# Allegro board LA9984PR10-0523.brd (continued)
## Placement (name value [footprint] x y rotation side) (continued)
PC803  -  [C_0603]  207.1 63.74 90 bottom
PC804  -  [C_0805]  212.73 73.84 0 top
PC805  -  [C_0805]  212.73 71.87 0 top
PC806  -  [C_0402]  204.23 53.96 0 bottom
PC807  -  [C_0603]  202.47 63.68 0 bottom
PC808  -  [C_0805]  212.73 69.92 0 top
PC809  -  [C_0402]  201.51 56.64 270 bottom
PC810  -  [C_0603]  201.51 59.49 180 top
PC811  -  [C_0603]  203.42 59.5 270 top
PC813  -  [C_0402]  205.32 57.28 270 top
PC814  -  [C_0402]  204.23 53.07 0 bottom
PC815  -  [C_0603]  211.61 64.24 0 bottom
PC816  -  [C_0402]  201.58 57.51 90 top
PC817  -  [C_0402]  201.58 53.06 90 bottom
PC818  -  [C_0402]  206.04 55.74 180 bottom
PC819  -  [C_0402]  199.11 61.27 180 bottom
PC820  -  [C_0402]  199.11 60.38 180 bottom
PC821  -  [C_0402]  201.59 56.63 180 top
PC831  -  [C_0402]  213.38 76.06 0 top
PC832  -  [C_0402]  213.38 75.17 0 top
PC835  -  [C_0603]  194.53 91.17 90 top
PC836  -  [C_D1]  204.31 87.44 270 top
PC837  -  [C_D1]  209.07 87.44 270 top
PC838  -  [C_D1]  198.15 86.61 270 bottom
PC839  -  [C_D1]  193.39 86.61 270 bottom
PC840  -  [C_0402]  181.44 124.21 0 top
PC841  -  [C_0402]  181.5 119.7 0 top
PC842  -  [C_0402]  182.08 120.94 90 top
PC843  -  [C_0402]  179.54 119.7 0 top
PC844  -  [C_0402]  177.34 119.25 180 top
PC845  -  [C_0402]  177.34 120.71 180 top
PC846  -  [C_0402]  176.49 122.68 0 top
PC847  -  [C_0402]  179.59 117.97 0 top
PC848  -  [C_0402]  181.37 117.97 0 top
PC849  -  [C_0402]  173.88 104.21 270 bottom
PC850  -  [C_0402]  178.21 121.86 270 top
PC851  -  [C_0402]  179.09 121.46 0 top
PC852  -  [C_0402]  178.73 117.72 180 top
PC853  -  [C_0402]  175.43 122.68 180 top
PC854  -  [C_0402]  174.46 119.25 0 top
PC855  -  [C_0402]  175.43 124.14 180 top
PC856  -  [C_0402]  179.28 124.21 0 top
PC857  -  [C_0402]  179.34 125.67 0 top
PC858  -  [C_0402]  181.44 125.67 0 top
PC859  -  [C_0402]  179.28 122.75 0 top
PC860  -  [C_0402]  181.44 122.75 0 top
PC861  -  [C_0402]  176.95 117.72 180 top
PC862  -  [C_0402]  178.2 114.48 0 top
PC863  -  [C_0402]  175.17 117.72 180 top
PC864  -  [C_0402]  176.36 124.14 0 top
PC865  -  [C_0402]  176.49 125.64 0 top
PC866  -  [C_0402]  174.46 120.71 0 top
PC867  -  [C_0603]  192.81 91.17 90 top
PC868  -  [C_0603]  196.31 91.17 90 top
PC869  -  [C_0402]  207.62 58.22 180 top
PC870  -  [C_0603]  198.02 91.17 90 top
PC871  -  [C_0402]  173.58 119.56 90 top
PC872  -  [C_0402]  172.18 119.03 90 top
PC873  -  [C_0402]  172.18 121.74 270 top
PC901  -  [C_0805]  97.44 124.74 90 top
PC902  -  [C_0805]  100.3 124.68 90 top
PC903  -  [C_0805]  102.77 124.68 90 top
PC904  -  [C_0805]  105.31 124.68 90 top
PC905  -  [C_0805]  107.79 124.68 90 top
PC906  -  [C_0805]  110.33 124.68 90 top
PC907  -  [C_0805]  112.8 124.68 90 top
PC908  -  [C_0805]  96.93 119.91 90 top
PC909  -  [C_0805]  100.65 139.56 0 top
PC910  -  [C_0805]  96.87 116.8 90 top
PC911  -  [C_0805]  97.35 137.34 0 top
PC912  -  [C_0805]  110.81 137.34 0 top
PC913  -  [C_0805]  110.75 139.5 0 top
PC914  -  [C_0805]  107.45 137.34 0 top
PC915  -  [C_0805]  107.38 139.5 0 top
PC916  -  [C_0805]  104.08 137.34 0 top
PC917  -  [C_0805]  100.71 137.34 0 top
PC918  -  [C_0805]  110.81 135.94 0 bottom
PC919  -  [C_0805]  107.45 135.94 0 bottom
PC920  -  [C_0805]  104.08 135.94 0 bottom
PC921  -  [C_0805]  100.71 135.94 0 bottom
PC922  -  [C_0805]  103.95 139.56 0 top
PC923  -  [C_0805]  97.35 135.94 0 bottom
PC1100  -  [C_0402]  178.64 175.38 0 top
PC1101  -  [C_0402]  178.64 176.26 0 top
PC1102  -  [C_0805]  178.82 177.6 0 top
PC1103  -  [C_0603]  183.16 172.26 90 top
PC1104  -  [C_0402]  188.19 174.04 180 bottom
PC1105  -  [C_0603]  183.67 175.06 90 top
PC1106  -  [C_0402]  181.45 172.12 90 top
PC1108  -  [C_MP6VU330MC6]  182.65 169.15 0 bottom
PC1200  -  [C_0402]  185.08 180.34 180 top
PC1201  -  [C_0805]  194.81 188.92 180 top
PC1202  -  [C_0805]  188.71 178.12 180 bottom
PC1203  -  [C_0402]  192.43 181.09 90 bottom
PC1204  -  [C_0805]  191.1 181.27 90 bottom
PC1205  -  [C_0603]  185.83 178.56 270 bottom
PC1206  -  [C_0805]  194.81 187.2 180 top
PC1207  -  [C_0805]  196.24 188.38 90 top
PC1209  -  [C_0402]  189.77 177.82 270 bottom
PC1210  -  [C_0603]  188.56 181.36 90 top
PC1211  -  [C_0805]  194.81 185.49 180 top
PC1212  -  [C_0603]  188.62 189.93 0 top
PC1213  -  [C_0603]  184.62 178.56 270 bottom
PC1214  -  [C_0402]  174.27 180.77 90 bottom
PC1300  -  [C_0805]  199.1 75.39 270 top
PC1301  -  [C_0805]  195 62.73 180 bottom
PC1302  -  [C_0402]  194.67 64.63 180 top
PC1303  -  [C_0805]  193.64 75.39 270 top
PC1304  -  [C_0402]  197.15 67.04 180 top
PC1305  -  [C_0805]  197.32 75.39 270 top
PC1306  -  [C_0402]  197.77 65.53 270 top
PC1307  -  [C_0402]  196.94 67.12 270 bottom
PC1308  -  [C_0805]  195.55 75.39 270 top
PD1  -  [IP4223CZ6_SO6]  142.24 187.06 270 bottom
PD2  -  [TVNST52302AB0_SOT523-3]  141.57 190.12 180 bottom
PD3  -  [TVNST52302AB0_SOT523-3]  144.87 187.45 270 bottom
PD101  -  [L03ESDL5V0CG3-2_SOT-523-3]  204.75 25.84 0 top
PD701  -  [RB751V-40_SOD323-2]  162.53 173.03 0 top
PH1  -  [R_0402]  106.19 115.75 0 top
PH501  -  [R_0402]  95.58 145.47 0 bottom
PH502  -  [R_0402]  111.93 146.17 180 bottom
PH800  -  [R_0402]  203.42 81.1 270 bottom
PJP100  -  [JUMP_43X118]  201.22 13.46 180 bottom
PJP101  -  [JUMP_43X118]  201.1 25.59 180 bottom
PJP102  -  [JUMP_43X118]  201.22 8.19 180 bottom
PJP103  -  [JUMP_43X118]  201.1 30.86 180 bottom
PJP200  -  [JUMP_43X118]  149.32 29.86 90 top
PJP201  -  [JUMP_43X118]  144.81 29.62 90 bottom
PJP203  -  [JUMP_43X39]  155.03 31.37 270 bottom
PJP300  -  [JUMP_43X118]  143.67 142.46 270 top
PJP400  -  [JUMP_43X79]  107.97 13.18 90 bottom
PJP401  -  [JUMP_43X79]  107.64 28.51 90 bottom
PJP600  -  [JUMP_43X79]  213.22 93.6 0 bottom
PJP601  -  [JUMP_43X79]  215.29 98.77 270 top
PJP1100  -  [JUMP_43X118]  182.78 164.33 270 bottom
PJP1101  -  [JUMP_43X118]  188.12 164.33 270 bottom
PJP1200  -  [JUMP_43X118]  194.47 183.31 270 top
PJP1300  -  [JUMP_43X79]  195.74 78.2 270 top
PJP1301  -  [JUMP_43X79]  194.66 60.77 270 bottom
PJPDC  -  [ACES_50299-00501-003_5P]  136.9 180.4 270 bottom
PL1  -  [CHT_C8BBPH853025_2P]  140.43 176.01 270 bottom
PL2  -  [CHT_C8BBPH853025_2P]  132.93 184.52 180 bottom
PL3  -  [CHENG_SMB3025500YA_2P]  155.86 182.27 90 bottom
PL4  -  [CHT_C8BBPH853025_2P]  132.87 168.14 180 bottom
PL100  -  [VISHAY_IHLP-2525CZ-01_2P]  214.79 10.16 180 bottom
PL101  -  [VISHAY_IHLP-2525CZ-01_2P]  215.93 31.63 180 bottom
PL102  -  [CYNTE_PCMB053T-1R0MS_2P]  222.5 20.64 180 bottom
PL200  -  [TAI-T_VMPI0703AR-1R0M-Z01_2P]  145.4 17.13 0 bottom
PL201  -  [L_1812-1806]  165.32 22.7 270 bottom
PL301  -  [CYNTE_PCMB063T-1R0MS_2P]  144.08 152.6 270 bottom
PL302  -  [L_1812-1806]  134.42 160.33 0 bottom
PL400  -  [TAIYO_NRS4018T1R0NDGJ_2P]  106.94 22.79 90 bottom
PL501  -  [L_1812-1806]  135.09 148.54 90 bottom
PL502  -  [TOKO_FDUE1040J-H-R36M-P3_4P]  109.67 142.17 180 bottom
PL600  -  [TAIYO_NRS4018T1R0NDGJ_2P]  219.55 96.84 90 bottom
PL701  -  [TOKO_FDVE1040-H-2R2M-P3_2P]  155.38 174.61 180 bottom
PL702  -  [CYNTE_PCMB053T-1R0MS_2P]  146.89 165.47 0 bottom
PL800  -  [L_1812-1806]  214.15 83.34 270 top
PL802  -  [MAG_MMD-12CE-R36M-M1L_2P]  210.72 78.67 90 bottom
PL1100  -  [TAI-T_HCB2012KF-121T50_2P]  175.16 179.39 90 top
PL1101  -  [PANAS_ETQP3W2R2WFN_2P]  177.13 172.2 90 bottom
PL1200  -  [CYNTE_PCMB063T-1R0MS_2P]  189.51 187.14 0 bottom
PL1201  -  [L_1812-1806]  195.52 177.99 180 bottom
PL1300  -  [VISHAY_IHLP-2525CZ-01_2P]  195.55 73.39 90 bottom
PQ1  -  [2N7002DW-T-R7_SOT363-6]  128.22 175.53 0 top
PQ2  -  [2N7002DW-T-R7_SOT363-6]  128.9 170.82 270 top
PQ3  -  [2N7002DW-T-R7_SOT363-6]  128.96 165.61 270 top
PQ4  -  [SSM3K7002FU_SC70-3]  128.17 181.35 0 top
PQ5  -  [RHU002N06_SOT323-3]  133.89 189.38 0 bottom
PQ6  -  [FDV301N_NL_SOT23-3]  128.97 188.58 90 bottom
PQ101  -  [SIS412DN-T1-GE3_POWERPAK8-5]  219.01 14.51 180 bottom
PQ102  -  [SIS412DN-T1-GE3_POWERPAK8-5]  213.22 17.38 0 bottom
PQ103  -  [SIS412DN-T1-GE3_POWERPAK8-5]  217.29 27.09 0 bottom
PQ104  -  [SIS412DN-T1-GE3_POWERPAK8-5]  215.27 24.22 180 bottom
PQ200  -  [SIS412DN-T1-GE3_POWERPAK8-5]  154.68 18.3 90 bottom
PQ201  -  [SIS412DN-T1-GE3_POWERPAK8-5]  157.04 16.47 270 bottom
PQ701  -  [CSD87312Q3E_SON8-4]  140.24 169.99 0 bottom
PQ702  -  [AO4407AL_SO8]  147.12 180.9 90 bottom
PQ703  -  [MDU1516URH_POWERDFN56-8-5]  155.98 171.31 180 top
PQ704  -  [MDU1516URH_POWERDFN56-8-5]  149.63 171.25 180 top
PQ705  -  [MDU1511RH_POWERDFN56-8-5]  159.54 173.24 90 top
PQ706  -  [SSM3K7002FU_SC70-3]  135.79 170.23 180 top
PQ708  -  [SSM3K7002FU_SC70-3]  171.48 175.12 0 top
PQ800  -  [SIR472DP-T1-GE3_POWERPAK8-5]  205.54 68.53 270 top
PQ801  -  [SIR818DP-T1_POWERPAK-SO8-5]  214.09 69.38 270 bottom
PQ802  -  [SIR818DP-T1_POWERPAK-SO8-5]  214.09 75.17 270 bottom
PQ803  -  [SIR472DP-T1-GE3_POWERPAK8-5]  205.59 76.41 270 top
PQ1100  -  [SIS412DN-T1-GE3_POWERPAK8-5]  175.38 174.26 0 top
PQ1101  -  [SIS412DN-T1-GE3_POWERPAK8-5]  180.28 176.87 270 bottom
PQ1201  -  [2N7002W-T-R7_SOT323-3]  177.09 181.5 270 bottom
PR1  -  [R_0402]  128.55 172.9 90 top
PR2  -  [R_0402]  126.27 174.17 90 top
PR3  -  [R_0402]  132.35 187.63 0 top
PR4  -  [R_0402]  130.57 187.63 0 top
PR5  -  [R_1206]  131.27 177.6 270 top
PR6  -  [R_0402]  132.5 184.71 180 top
PR7  -  [R_0402]  128.86 179.5 0 top
PR8  -  [R_0402]  134.22 189.47 180 top
PR9  -  [R_0402]  134.28 184.71 180 top
PR10  -  [R_0402]  129.77 178.61 180 top
PR15  -  [R_0402]  138.54 186.93 180 bottom
PR16  -  [R_0402]  136.76 186.93 180 bottom
PR17  -  [R_0402]  139.17 188.72 180 bottom
PR18  -  [R_0402]  141.88 185.66 0 top
PR20  -  [R_0402]  141.88 186.55 0 top
PR23  -  [R_0402]  129.94 181.92 0 top
PR24  -  [R_0402]  181.96 47.03 90 bottom
PR26  -  [R_0402]  130.85 183.69 180 top
PR27  -  [R_0402]  129.11 180.9 0 top
PR28  -  [R_0402]  128.38 168.39 180 top
PR29  -  [R_0402]  127.65 172.01 0 top
PR30  -  [R_0402]  127.54 163.81 90 top
PR31  -  [R_0402]  131.98 169.71 90 top
PR32  -  [R_0402]  132.11 164.72 270 top
PR33  -  [R_0402]  130.51 168.33 0 top
PR100  -  [R0402_0OHM]  204.56 27.24 90 top
PR101  -  [R0402_0OHM]  205.45 27.24 90 top
PR102  -  [R_0402]  203.67 27.24 90 top
PR103  -  [R_0402]  207.75 15.61 90 top
PR104  -  [R_0402]  204.05 21.34 180 top
PR105  -  [R_0402]  204.05 22.23 180 top
PR106  -  [R_0402]  204.07 22.33 180 bottom
PR107  -  [R_0402]  203.14 17.34 0 top
PR108  -  [R_0402]  204.05 16.45 180 top
PR109  -  [R_0402]  203.14 19.12 0 top
PR111  -  [R_0402]  208.36 23.93 90 top
PR112  -  [R_1206]  211.48 27.05 270 bottom
PR113  -  [R_1206]  211.17 14.61 90 bottom
PR114  -  [R_0402]  206.58 23.93 90 top
PR200  -  [R_0603]  154.85 24.96 90 bottom
PR201  -  [R0402_0OHM]  162.92 27.23 180 bottom
PR202  -  [R0402_0OHM]  162.92 29.01 180 bottom
PR203  -  [R_1206]  161.32 12.75 0 bottom
PR204  -  [R_0402]  161.47 31.12 180 bottom
PR205  -  [R_0402]  158.59 22.29 90 bottom
PR206  -  [R_0603]  162.09 23.43 270 bottom
PR207  -  [R_0402]  161.47 30.23 180 bottom
PR208  -  [R_0402]  162.92 25.45 180 bottom
PR300  -  [R0402_0OHM]  148.17 150.35 0 bottom
PR301  -  [R_0402]  148.17 151.24 0 bottom
PR302  -  [R_1206]  139.54 148.57 90 bottom
PR303  -  [R0603_0OHM]  147.04 158.86 0 bottom
PR304  -  [R_0402]  149.08 154.79 180 bottom
PR305  -  [R_0402]  148.62 155.73 90 bottom
PR306  -  [R_0402]  148.17 153.9 0 bottom
PR307  -  [R_0402]  149.39 157.51 90 bottom
PR308  -  [R_0402]  149.08 153.02 180 bottom
PR401  -  [R0402_0OHM]  107.46 20.17 180 top
PR402  -  [R_0402]  109.06 19.82 0 top
PR403  -  [R_0402]  109.98 18.93 180 top
PR404  -  [R_0402]  107.46 19.26 180 top
PR405  -  [R_0603]  106.22 19.1 180 bottom
PR501  -  [R_0402]  88.61 143.23 90 bottom
PR502  -  [R_0402]  85.94 143.23 90 bottom
PR503  -  [R_0402]  88.48 140.95 90 top
PR504  -  [R_0402]  86.83 143.23 90 bottom
PR505  -  [R_0402]  86.71 140.95 90 top
PR506  -  [R_0402]  85.82 140.95 90 top
PR507  -  [R_0402]  87.72 143.23 90 bottom
PR508  -  [R_0402]  91.66 144.2 270 bottom
PR509  -  [R_0402]  87.6 140.95 90 top
PR510  -  [R_0402]  87.01 139.24 0 top
PR512  -  [R_0402]  89.37 140.95 90 top
PR513  -  [R_0402]  91.15 140.95 90 top
PR514  -  [R_0402]  90.77 143.3 90 bottom
PR515  -  [R_0402]  92.98 143.75 0 bottom
PR516  -  [R_0603]  83.98 137.78 0 bottom
PR517  -  [R_0402]  92.98 142.86 0 bottom
PR518  -  [R_0402]  92.93 145.07 90 bottom
PR519  -  [R_0603]  88.87 133.9 90 bottom
PR522  -  [R0402_0OHM]  85.46 141.02 180 bottom
PR524  -  [R_0402]  84.55 139.24 0 bottom
PR526  -  [R_0402]  87.79 134.6 90 bottom
PR528  -  [R_0402]  86.9 134.6 90 bottom
PR529  -  [R_0402]  92.66 134.61 0 bottom
PR530  -  [R_0402]  84.53 136.7 0 bottom
PR531  -  [R_0402]  90.9 134.67 90 bottom
PR532  -  [R_0402]  93.58 135.5 180 bottom
PR533  -  [R_0402]  85.45 136.7 180 top
PR534  -  [R_1206]  108.42 145.21 0 top
PR535  -  [R0402_0OHM]  85.46 140.13 180 bottom
PR536  -  [R_0603]  116.82 141.9 0 bottom
PR540  -  [R_0402]  84.53 137.59 0 top
PR601  -  [R0402_0OHM]  218.29 95.37 180 top
PR602  -  [R_0402]  221.26 91.8 90 bottom
PR603  -  [R_0402]  222.16 90.92 180 bottom
PR604  -  [R_0402]  219.17 95.38 270 top
PR605  -  [R_0603]  216.06 97.14 270 bottom
PR701  -  [R_0402]  142.9 165.9 90 bottom
PR702  -  [R_1206_4P-D]  139.7 164.2 0 bottom
PR703  -  [R_0402]  143.79 166.82 270 bottom
PR704  -  [R0402_0OHM]  166.78 167.96 270 bottom
PR705  -  [R_1206]  164.49 165.09 90 top
PR706  -  [R_0402]  147.36 185.92 180 bottom
PR707  -  [R_0402]  169.07 166.98 90 top
PR708  -  [R0402_0OHM]  167.67 175.05 90 top
PR709  -  [R_0603]  163.92 171.57 180 top
PR710  -  [R0402_0OHM]  168.56 175.05 90 top
PR711  -  [R_0402]  172.25 169.22 180 top
PR712  -  [R_0402]  170.02 167.9 270 top
PR713  -  [R_0402]  171.34 173.66 0 top
PR714  -  [R0402_0OHM]  172.25 172.77 180 top
PR715  -  [R0402_0OHM]  172.25 171.88 180 top
PR716  -  [R_1206_4P-D]  143.73 178.65 90 bottom
PR717  -  [R0402_0OHM]  167.67 167.96 270 bottom
PR720  -  [R_1206]  138.2 171.95 180 top
PR721  -  [R_0402]  143.81 167.69 180 bottom
PR722  -  [R_1206]  157 179.12 0 top
PR723  -  [R_0402]  171.34 168.33 0 top
PR724  -  [R_0402]  171.07 178.23 0 top
PR802  -  [R0603_0OHM]  201.39 62.09 90 bottom
PR803  -  [R0402_0OHM]  209.91 58.03 180 bottom
PR804  -  [R0402_0OHM]  206.71 59.11 0 top
PR805  -  [R_1206]  214.21 63.86 0 bottom
PR806  -  [R0402_0OHM]  209.91 58.92 180 bottom
PR807  -  [R0402_0OHM]  209.91 60.69 180 bottom
PR808  -  [R_0402]  209.91 56.25 180 bottom
PR809  -  [R0402_0OHM]  209.91 59.81 180 bottom
PR810  -  [R0402_0OHM]  209.91 62.47 180 bottom
PR811  -  [R0402_0OHM]  209.91 63.36 180 bottom
PR812  -  [R0402_0OHM]  209.91 61.58 180 bottom
PR813  -  [R_0402]  203.37 53.96 180 bottom
PR814  -  [R0603_0OHM]  205.9 63.74 90 bottom
PR815  -  [R_0402]  206.72 56.36 90 top
PR816  -  [R_0402]  199.11 58.6 180 bottom
PR817  -  [R_0402]  206.04 54.85 180 bottom
PR818  -  [R_0402]  203.37 53.07 180 bottom
PR819  -  [R_0402]  211.22 62.47 0 bottom
PR820  -  [R_0402]  205.32 55.5 270 top
PR821  -  [R_0402]  204.24 55.75 270 bottom
PR822  -  [R_0603]  201.51 60.69 180 bottom
PR823  -  [R0603_0OHM]  201.51 60.69 180 top
PR824  -  [R_0402]  201.58 62.68 270 top
PR825  -  [R_0402]  201.59 57.52 180 bottom
PR826  -  [R_0402]  213.91 61.52 180 bottom
PR827  -  [R_0402]  199.11 59.49 180 bottom
PR828  -  [R_0402]  213.91 62.41 180 bottom
PR829  -  [R_0402]  199.1 63.06 270 bottom
PR830  -  [R0402_0OHM]  198.21 63.06 270 bottom
PR833  -  [R_0402]  200.69 58.42 270 top
PR834  -  [R_0402]  211.22 61.58 0 bottom
PR835  -  [R_0402]  213.91 60 180 bottom
PR836  -  [R_0402]  211.22 60 0 bottom
PR837  -  [R_0402]  213.91 59.11 180 bottom
PR838  -  [R_0402]  211.22 59.11 0 bottom
PR839  -  [R_0402]  213.91 57.58 180 bottom
PR840  -  [R_0402]  211.22 57.58 0 bottom
PR842  -  [R_0402]  208.99 57.14 0 bottom
PR845  -  [R0402_0OHM]  200.63 56.64 270 bottom
PR846  -  [R0402_0OHM]  203.37 55.74 180 bottom
PR1101  -  [R_0603]  185.07 171.18 180 top
PR1102  -  [R_0402]  187.28 173.15 0 bottom
PR1103  -  [R0402_0OHM]  189.89 175.2 270 top
PR1104  -  [R_1206]  177.57 172.45 0 top
PR1105  -  [R_0402]  188.19 175.82 180 bottom
PR1107  -  [R_0402]  189.89 174.88 270 bottom
PR1108  -  [R_0402]  188.19 174.93 180 bottom
PR1110  -  [R_0402]  189.21 171.69 180 top
PR1200  -  [R0603_0OHM]  187.29 180.22 0 top
PR1201  -  [R_0402]  185.08 181.23 180 top
PR1202  -  [R_0402]  185.08 179.45 180 top
PR1203  -  [R_0402]  183.54 178.04 90 bottom
PR1204  -  [R_0402]  185.08 181.61 180 bottom
PR1206  -  [R0402_0OHM]  186.72 182.11 90 top
PR1207  -  [R_1206]  189.2 185.87 90 top
PR1208  -  [R_0402]  179.47 181.49 0 bottom
PR1209  -  [R_0402]  185.08 180.72 180 bottom
PR1210  -  [R0402_0OHM]  180.38 180.6 180 bottom
PR1211  -  [R_0402]  185.08 179.83 180 bottom
PR1212  -  [R_0402]  174.32 179.64 0 bottom
PR1213  -  [R_0402]  175.16 184.38 270 bottom
PR1214  -  [R_0402]  174.27 183.47 270 bottom
PR1300  -  [R_0402]  197.84 68 180 bottom
PR1301  -  [R_0402]  195.99 64.62 90 top
PR1302  -  [R_0402]  196.88 65.53 270 top
PR1303  -  [R_1206]  196.62 70.92 270 top
PR1304  -  [R_0402]  197.89 67.12 270 bottom
PU100  -  [TPS51225CRUKR_QFN20_3X3]  205.6 21.02 270 top
PU200  -  [RT8207MZQW_WQFN20_3X3]  157.71 28.39 0 bottom
PU300  -  [SY8206DQNC_QFN10_3X3]  145.59 155.64 90 bottom
PU400  -  [SY8003DFC_DFN8_2X2]  108.75 16.34 180 bottom
PU501  -  [TPS51622RSM_QFN32_4X4]  87.18 138.03 90 bottom
PU502  -  [CSD97374CQ4M_SON8_3P5X4P5-S]  111.9 141.64 90 bottom
PU600  -  [SY8003DFC_DFN8_2X2]  220.04 92.17 180 bottom
PU701  -  [BQ24738RGRR_QFN20_3P5X3P5]  166.99 169.71 0 top
PU800  -  [ISL62881HRZ-T_QFN28_4X4]  206.59 57.47 180 bottom
PU1100  -  [TPS51212DSCR_SON10_3X3]  188.26 173.3 90 top
PU1200  -  [SY8206DQNC_QFN10_3X3]  186.83 182.29 270 bottom
PU1300  -  [SY8036DBC_DFN10_3X3]  193.66 67.58 0 bottom
Q8  -  [2N7002K_SOT23-3]  88.87 25.03 180 top
Q2307  -  [2N7002K_SOT23-3]  182.97 62.18 180 top
Q2308  -  [2N7002K_SOT23-3]  147.9 123.18 270 top
QA5  -  [DMN66D0LDW-7_SOT363-6]  26.48 28.52 270 bottom
QA6  -  [DMN66D0LDW-7_SOT363-6]  15.8 22.71 90 bottom
QC1  -  [DMN66D0LDW-7_SOT363-6]  144.74 112.08 0 bottom
QC3  -  [2N7002K_SOT23-3]  134.41 133.61 180 bottom
QD2  -  [BSS138-G_SOT23-3]  80.9 56.84 270 top
QD18  -  [2N7002K_SOT23-3]  47.97 15.91 0 top
QD19  -  [2N7002K_SOT23-3]  54.21 14.89 0 top
QD20  -  [2N7002K_SOT23-3]  58.27 14.89 0 top
QE4  -  [2N7002BKW_SOT323-3]  36.73 116.91 90 top
QE5  -  [SI3456BDV-T1-E3_TSOP6]  43.08 117.16 270 bottom
QH1  -  [DMN66D0LDW-7_SOT363-6]  146.31 115.89 90 bottom
QM30  -  [2N7002K_SOT23-3]  101.42 149.33 90 top
QS2  -  [SI3456BDV-T1-E3_TSOP6]  220.85 123.1 0 bottom
QS3  -  [2N7002KW_SOT323-3]  221.16 127.29 0 bottom
QV14  -  [DMN66D0LDW-7_SOT363-6]  188.48 103.23 0 bottom
QV15  -  [DMN66D0LDW-7_SOT363-6]  178.54 95.84 180 top
QV22  -  [AP2301GN-HF_SOT23-3]  184.15 95.74 90 bottom
QV24  -  [2N7002K_SOT23-3]  179 92.25 270 bottom
QV25  -  [2N7002K_SOT23-3]  174.36 92.06 270 bottom
QV28  -  [2N7002K_SOT23-3]  183.16 92.54 0 top
QX1  -  [2N7002KW_SOT323-3]  225.01 178.89 90 top
QX2  -  [SI3457CDV-T1-GE3_TSOP6]  231.15 178.94 180 top
QX3  -  [2N7002K_SOT23-3]  19.12 108.83 90 bottom
QX4  -  [DMN66D0LDW-7_SOT363-6]  15.19 108.77 0 top
QX5  -  [MMBT3904_NL_SOT23-3]  16.6 115.15 180 bottom
QX6  -  [DMN66D0LDW-7_SOT363-6]  196.11 163.63 90 top
R1  -  [R_0402]  93.64 136.07 180 top
R2  -  [R_0402]  91.86 136.07 180 top
R10  -  [R_0402]  87.34 26.73 270 top
R16  -  [R_0402]  87.84 21.2 0 top
R159  -  [R_0402]  147.53 104.57 0 top
R245  -  [R_0603]  93.12 131.94 90 bottom
R248  -  [R0402_0OHM]  80.85 119.81 0 bottom
R250  -  [R_0402]  91.98 124.12 90 top
R251  -  [R0402_0OHM]  90.28 131.69 270 bottom
R252  -  [R_0402]  80.85 120.7 0 bottom
R253  -  [R_0402]  81.77 122.61 180 bottom
R254  -  [R_0402]  84.12 120.7 180 bottom
R255  -  [R_0402]  83.2 122.99 0 bottom
R256  -  [R_0402]  79.92 121.59 0 bottom
R257  -  [R0402_0OHM]  79.92 122.54 180 bottom
R264  -  [R0603_0OHM]  150.97 106.67 180 top
R265  -  [R0402_0OHM]  118.33 100.2 270 top
R267  -  [R0805_0OHM]  123.83 143.17 0 bottom
R286  -  [R_0402]  91.16 131.68 270 bottom
R416  -  [R0402_0OHM]  141.27 28.64 180 bottom
R2313  -  [R_0402]  187.14 21.02 0 top
R2314  -  [R_0603]  184.62 64.5 270 top
R2315  -  [R_0603]  146.9 126.1 270 top
R2318  -  [R_0402]  187.07 17.66 0 top
R2329  -  [R_0402]  140.87 111.07 0 bottom
R2330  -  [R_0402]  135.28 105.67 270 bottom
R2331  -  [R_0402]  147.04 111.02 270 bottom
R2332  -  [R_0402]  147.93 112.07 180 bottom
R2333  -  [R_0402]  142.55 117.87 180 bottom
R2334  -  [R_0402]  142.55 118.76 180 bottom
R2335  -  [R_0402]  142.55 119.64 180 bottom
R2336  -  [R_0402]  125.84 98.41 180 top
R2337  -  [R_0402]  134.01 101.66 270 bottom
R2338  -  [R_0402]  133.12 101.66 270 bottom
R2341  -  [R_0402]  75.29 116.07 180 top
R2346  -  [R_0402]  79.91 124.51 90 bottom
R2347  -  [R_0402]  83.94 53.34 180 top
R2348  -  [R_0402]  84.77 57.15 0 top
R2349  -  [R_0402]  84.77 58.04 0 top
R2350  -  [R_0402]  84.77 56.26 0 top
R2351  -  [R_0402]  83.94 54.23 180 top
R2352  -  [R_0402]  84.77 55.37 0 top
R2354  -  [R_0402]  187.42 34.71 90 top
R2355  -  [R_0402]  44.4 24.69 0 top
R2356  -  [R_0402]  127.24 99.05 90 bottom
R2357  -  [R_0402]  130.01 98.5 90 bottom
R2358  -  [R_0402]  129.05 99.05 90 bottom
R2359  -  [R_0402]  128.16 99.05 90 bottom
RA1  -  [R_0402]  42.83 32.45 270 top
RA2  -  [R_0402]  22.5 28.25 0 bottom
RA3  -  [R_0402]  27.79 24.51 180 bottom
RA4  -  [R0402_0OHM]  42.83 29.76 90 top
RA5  -  [R_0402]  17.62 27.5 270 bottom
RA6  -  [R_0402]  15.78 27.5 270 bottom
RA7  -  [R_0402]  16.68 27.5 270 bottom
RA8  -  [R_0402]  37.76 18.21 180 top
RA9  -  [R_0402]  37.76 19.09 180 top
RA19  -  [R_0402]  48.87 27.8 180 top
RA29  -  [R0603_0OHM]  17.36 11.56 0 bottom
RA30  -  [R0603_0OHM]  27.97 15.18 270 bottom
RA31  -  [R0603_0OHM]  35.53 30.98 90 top
RA32  -  [R0603_0OHM]  39.14 16.31 0 top
RA51  -  [R_0402]  41.94 29.76 90 top
RA53  -  [R_0402]  23.88 25.47 0 top
RA55  -  [R_0402]  29.19 25.61 270 top
RA56  -  [R_0402]  28.3 25.61 270 top
RA79  -  [R_0402]  46.18 28.69 0 top
RA80  -  [R_0402]  28.86 22.47 90 bottom
RA81  -  [R_0402]  47.1 29.58 180 top
RA82  -  [R_0402]  27.97 22.47 90 bottom
RA83  -  [R_0402]  32.3 24.31 180 top
RA84  -  [R_0402]  31.54 26.1 180 top
RA130  -  [R_0402]  45.32 25.64 180 top
RA153  -  [R_0402]  40.73 30.93 270 top
RA165  -  [R_0402]  34.08 24.31 180 top
RA166  -  [R_0402]  34.08 25.2 180 top
RA1109  -  [R_0402]  23.88 24.58 0 top
RC1  -  [R_0402]  132.3 99.32 270 bottom
RC2  -  [R_0402]  133.19 98.55 270 bottom
RC3  -  [R_0402]  125.45 99.05 90 bottom
RC4  -  [R_0402]  146 100.26 0 bottom
RC5  -  [R_0402]  130.34 96.77 90 top
RC6  -  [R_0402]  131.23 96.77 90 top
RC7  -  [R_0402]  134.9 100.75 90 bottom
RC8  -  [R_0402]  126.34 99.05 90 bottom
RC9  -  [R_0402]  135.08 117.72 0 top
RC10  -  [R_0402]  110.7 15.86 0 bottom
RC11  -  [R_0402]  131.61 120.32 180 top
RC12  -  [R_0402]  116.23 136.47 0 top
RC13  -  [R_0402]  115.54 131.23 90 bottom
RC14  -  [R_0402]  97.96 93.08 90 bottom
RC15  -  [R_0402]  94.59 93.08 90 bottom
RC16  -  [R_0402]  96.99 92.45 180 bottom
RC17  -  [R_0402]  97.07 95.75 90 bottom
RC18  -  [R_0402]  94.4 95.75 90 bottom
RC19  -  [R_0402]  96.18 95.75 90 bottom
RC20  -  [R_0402]  97.05 94.87 0 bottom
RC21  -  [R_0402]  94.41 94.87 180 bottom
RC22  -  [R_0402]  96.19 94.87 180 bottom
RC23  -  [R_0402]  97.96 96.66 270 bottom
RC24  -  [R_0402]  93.51 96.66 270 bottom
RC25  -  [R_0402]  95.29 96.66 270 bottom
RC26  -  [R0402_0OHM]  59.97 106.16 90 bottom
RC27  -  [R_0402]  136.82 98.4 180 top
RC28  -  [R_0402]  148.42 110.99 0 bottom
RC29  -  [R_0402]  146.96 113.19 0 bottom
RC31  -  [R_0402]  147.87 111.05 180 top
RC32  -  [R_0402]  143.46 116.45 0 bottom
RC33  -  [R0402_0OHM]  126.98 100.19 180 top
RC34  -  [R_0402]  130.9 112.27 270 top
RC35  -  [R_0402]  134.08 99.32 270 top
RC36  -  [R_0402]  129.77 116.36 180 top
RC37  -  [R_0402]  133.37 111.31 180 bottom
RC41  -  [R0402_0OHM]  128 99.06 180 top
RC42  -  [R0402_0OHM]  134.97 98.4 90 top
RC43  -  [R0402_0OHM]  74.98 108.46 180 bottom
RC44  -  [R0402_0OHM]  74.54 106.22 180 bottom
RC45  -  [R0402_0OHM]  74.54 107.13 180 bottom
RC46  -  [R0402_0OHM]  65.94 106.37 0 bottom
RC48  -  [R_0402]  65.44 92.13 90 bottom
RC49  -  [R_0402]  63.67 92.13 90 bottom
RC50  -  [R_0402]  62.78 92.13 90 bottom
RC51  -  [R_0402]  61.82 104.6 270 bottom
RC52  -  [R_0402]  61.89 92.13 90 bottom
RC56  -  [R_0402]  56.99 103.24 90 bottom
RC57  -  [R0402_0OHM]  75.29 116.96 180 top
RC58  -  [R_0402]  89.17 121.59 0 top
RC59  -  [R0402_0OHM]  84.62 112.7 180 bottom
RC60  -  [R_0402]  88.3 122.04 90 top
RC62  -  [R_0402]  83.71 113.59 0 bottom
RC63  -  [R_0402]  89.77 114.03 180 top
RC64  -  [R_0402]  62.78 90.7 270 bottom
RC65  -  [R_0402]  83.71 111.81 0 bottom
RC66  -  [R_0402]  89.2 130.86 180 bottom
RC67  -  [R_0402]  89.56 122.94 0 top
RC68  -  [R_0402]  89.32 100.16 270 top
RC69  -  [R_0402]  90.21 100.16 270 top
RC70  -  [R_0402]  88.43 100.16 270 top
RC71  -  [R_0402]  117.75 126.1 0 top
RC72  -  [R_0402]  103.34 130.74 90 bottom
RC73  -  [R_0402]  137.13 120.46 270 bottom
RC74  -  [R_0402]  125 118.21 90 top
RC75  -  [R_0402]  131.04 136.82 180 bottom
RC76  -  [R_0402]  136.25 121.34 180 bottom
RC77  -  [R_0402]  129.45 120.58 180 top
RC78  -  [R_0402]  134.73 130.99 90 bottom
RC81  -  [R0402_0OHM]  129.25 135.93 90 bottom
RC84  -  [R_0402]  131.04 135.93 180 bottom
RC87  -  [R_0402]  126.27 125.71 90 top
RC88  -  [R_0402]  133.49 121.21 0 bottom
RC89  -  [R_0402]  133.82 131.9 270 bottom
RC90  -  [R_0402]  122.51 112.42 90 top
RC91  -  [R_0402]  113.74 131.31 0 bottom
RC97  -  [R_0402]  130.89 110.48 0 top
RC98  -  [R_0402]  128.54 121.46 0 top
RC99  -  [R_0402]  134.2 117.9 90 top
RC100  -  [R_0402]  136 118.61 180 top
RC101  -  [R_0402]  124.28 99.16 270 bottom
RC102  -  [R_0402]  143.85 121.67 0 bottom
RC103  -  [R_0402]  148.19 114.61 180 bottom
RC104  -  [R_0402]  141.78 111.95 180 bottom
RC105  -  [R_0402]  132.86 132.72 270 bottom
RC106  -  [R_0402]  136.25 124 180 bottom
RC107  -  [R_0402]  143.73 112.22 270 bottom
RC108  -  [R_0402]  136.64 123.13 180 bottom
RC110  -  [R_0402]  145 113.93 0 bottom
RC111  -  [R_0402]  136.63 122.23 180 bottom
RC112  -  [R_0402]  134.6 121.34 180 top
RC113  -  [R_0402]  133.68 120.45 0 top
RC116  -  [R_0402]  133.49 120.32 0 bottom
RC118  -  [R_0402]  136.25 127.88 180 bottom
RC119  -  [R_0402]  136.25 120.45 180 bottom
RC120  -  [R_0402]  146.11 114.81 180 bottom
RC121  -  [R_0402]  136.5 116.26 180 bottom
RC122  -  [R_0402]  134.41 127.59 180 bottom
RC123  -  [R_0402]  133.49 122.1 0 bottom
RC124  -  [R_0402]  148.43 109.22 0 bottom
RC125  -  [R_0402]  148.43 110.11 0 bottom
RC126  -  [R0603_0OHM]  123.35 132.64 90 bottom
RC127  -  [R_0402]  122.65 94.35 90 top
RC128  -  [R_0402]  123.54 94.35 90 top
RC129  -  [R_0402]  120.81 120.03 270 top
RC130  -  [R_0402]  85.56 112.69 90 bottom
RC131  -  [R_0402]  124.43 132.63 90 bottom
RC132  -  [R_0402]  91.72 117.67 0 top
RC133  -  [R_0402]  122.27 133.48 270 bottom
RC134  -  [R_0402]  123.39 99.16 270 bottom
RC135  -  [R_0402]  84.62 110.92 180 bottom
RC138  -  [R_0402]  82.6 115.51 180 bottom
RC139  -  [R_0402]  108.36 131.7 270 bottom
RC140  -  [R_0402]  109.31 131.7 270 bottom
RC141  -  [R0402_0OHM]  84.12 122.04 180 bottom
RC163  -  [R_0402]  89.58 126.04 180 top
RC362  -  [R_0402]  60.06 104.6 270 bottom
RD1  -  [R0402_0OHM]  43.29 76.65 180 top
RD3  -  [R_0402]  80.04 59.2 270 top
RD4  -  [R0402_0OHM]  83.46 65.46 0 top
RD5  -  [R0402_0OHM]  84.37 64.57 180 top
RD6  -  [R_0402]  102.44 70.79 0 top
RD7  -  [R_0402]  102.44 69.9 0 top
RD8  -  [R0402_0OHM]  121.33 72.76 180 top
RD10  -  [R0402_0OHM]  162.07 64.57 0 top
RD12  -  [R_0402]  182.79 67.62 180 top
RD13  -  [R_0402]  182.78 72.49 90 top
RD14  -  [R_0402]  25.82 11.88 180 top
RD15  -  [R_0402]  35.03 11.88 180 top
RD16  -  [R_0402]  42.22 14.15 270 top
RD17  -  [R_0402]  41.33 14.15 270 top
RD18  -  [R_0402]  51.38 14.09 180 top
RD45  -  [R_0402]  48.92 19.79 90 top
RD46  -  [R_0402]  51.34 15.92 270 top
RD47  -  [R_0402]  55.1 18.82 180 top
RD48  -  [R_0402]  58.21 19.79 0 top
RD49  -  [R_0402]  54.19 19.79 180 top
RD50  -  [R_0402]  59.24 18.76 0 top
RD51  -  [R_0402]  55.81 14.01 0 top
RD52  -  [R_0402]  53.33 18.82 180 top
RE1  -  [R_0402]  93.77 123.81 180 top
RE2  -  [R_0402]  132.13 100.88 180 bottom
RE3  -  [R_0402]  197.2 55.79 90 top
RE5  -  [R_0402]  195.42 56.71 270 top
RE7  -  [R_0402]  192.05 56.67 270 top
RE8  -  [R_0402]  199.47 40.95 0 top
RE9  -  [R_0402]  187.04 56.2 270 top
RE10  -  [R_0402]  186.15 56.2 270 top
RE11  -  [R_0402]  181.69 35.94 180 top
RE12  -  [R_0402]  179.56 42.28 180 top
RE18  -  [R_0402]  195.93 35.82 270 top
RE36  -  [R_0402]  178.58 47.87 0 top
RE37  -  [R0402_0OHM]  127.84 100.19 0 top
RE43  -  [R_0402]  179.43 43.74 180 top
RE44  -  [R0402_0OHM]  180.5 56.39 270 top
RE47  -  [R_0402]  178.27 52.36 90 top
RE49  -  [R_0402]  194.54 29.58 180 top
RE50  -  [R_0402]  50.97 107.24 180 bottom
RE58  -  [R_0402]  38.7 115.19 180 top
RE59  -  [R_0805]  37.87 106.43 90 top
RE60  -  [R_0402]  228.31 158.41 90 bottom
RE68  -  [R_0402]  36.35 117.92 180 top
RE71  -  [R_0402]  178.51 44.63 0 top
RE326  -  [R_0402]  179.49 50.92 180 top
RG1  -  [R_0402]  67.25 49.51 270 top
RG2  -  [R_0402]  61.08 49.43 270 top
RG3  -  [R_0402]  131.96 99.02 90 top
RG4  -  [R_0402]  63.26 48.49 90 top
RG5  -  [R_0402]  65.19 42.52 270 top
RG6  -  [R_0402]  119.13 137.65 90 top
RG7  -  [R_0402]  174.01 101.15 270 bottom
RG8  -  [R_0402]  35.16 79.89 90 bottom
RL19  -  [R_0603]  20.29 88.06 270 top
RL20  -  [R_0603]  20.29 84.25 90 top
RL27  -  [R_0402]  42.88 83.05 0 bottom
RL31  -  [R_0402]  35.08 83.03 90 bottom
RL33  -  [R_0402]  42.97 89.21 180 bottom
RL34  -  [R_0402]  42.97 87.43 180 bottom
RL35  -  [R_0402]  42.97 88.32 180 bottom
RL37  -  [R_0402]  37.05 91.86 90 bottom
RL38  -  [R_0402]  41.43 83.41 90 bottom
RM11  -  [R_0402]  114.09 149.7 90 top
RM13  -  [R_0402]  114.98 150.61 270 top
RM25  -  [R0805_0OHM]  119.68 150.22 180 top
RM26  -  [R0805_0OHM]  95 150.47 180 top
RM110  -  [R_0402]  103.17 150.68 270 top
RP36  -  [RP_0804_8P4R]  189.4 56.25 90 top
RP37  -  [RP_0804_8P4R]  138.97 117.17 0 bottom
RP39  -  [RP_0804_8P4R]  140.12 121.47 180 bottom
RP40  -  [RP_0804_8P4R]  138.46 114.05 0 bottom
RP41  -  [RP_0804_8P4R]  142.34 113.3 0 bottom
RP42  -  [RP_0804_8P4R]  148.18 114.75 180 top
RP43  -  [RP_0804_8P4R]  143.11 124.33 180 bottom
RP44  -  [RP_0804_8P4R]  86.46 125.71 180 bottom
RP45  -  [RP_0804_8P4R]  74.94 113.41 180 top
RP46  -  [RP_0804_8P4R]  60.6 91.49 90 bottom
RP47  -  [RP_0804_8P4R]  175.62 107.87 90 top
RP48  -  [RP_0804_8P4R]  86.89 113 0 bottom
RP49  -  [RP_0804_8P4R]  138.46 111.25 0 bottom
RP50  -  [RP_0804_8P4R]  132.18 113.35 180 top
RP51  -  [RP_0804_8P4R]  130.95 132.07 90 bottom
RP52  -  [RP_0804_8P4R]  20.02 111.75 90 bottom
RP53  -  [RP_0804_8P4R]  135.72 125.29 0 bottom
RP54  -  [RP_0804_8P4R]  132.18 116.14 180 top
RP55  -  [RP_0804_8P4R]  139.59 99.46 270 top
RP56  -  [RP_0804_8P4R]  200.06 177.48 180 top
RP57  -  [RP_0804_8P4R]  196.02 166.6 180 top
RP58  -  [RP_0804_8P4R]  15.21 98.49 180 top
RP59  -  [RP_0804_8P4R]  16.61 103.95 180 top
RP60  -  [RP_0804_8P4R]  184 107.94 90 top
RR1  -  [R_0402]  175.03 20.83 270 top
RR2  -  [R_0402]  178.21 28.74 90 top
RR3  -  [R_0402]  180.86 23.74 0 top
RS6  -  [R_0402]  223.05 125.9 0 bottom
RS7  -  [R_0402]  218.76 52.52 0 top
RS8  -  [R_0402]  218.76 51.58 0 top
RV1  -  [R_0402]  218.6 145.1 270 bottom
RV2  -  [R_0402]  218.52 142.42 0 bottom
RV3  -  [R_0402]  218.46 128.45 0 bottom
RV4  -  [R_0402]  218.46 126.67 0 bottom
RV5  -  [R_0402]  201.41 135.69 180 bottom
RV6  -  [R_0402]  200.5 133.91 0 bottom
RV7  -  [R_0402]  218.71 126.67 0 top
RV8  -  [R_0402]  219.62 128.45 180 top
RV9  -  [R_0402]  206.4 144.63 90 top
RV10  -  [R_0402]  204.63 145.54 270 top
RV11  -  [R_0402]  201.46 133.87 180 top
RV12  -  [R_0402]  200.55 131.69 0 top
RV13  -  [R_0402]  212.64 104.07 180 bottom
RV14  -  [R_0402]  211.73 102.29 0 bottom
RV15  -  [R_0402]  206.15 103.82 270 bottom
RV16  -  [R_0402]  204.37 102.91 90 bottom
RV17  -  [R_0402]  201.22 113.89 180 top
RV19  -  [R_0402]  200.31 115.67 0 top
RV20  -  [R_0402]  214.53 102.11 270 top
RV21  -  [R_0402]  212.75 101.19 90 top
RV22  -  [R_0402]  218.46 122.1 0 top
RV23  -  [R_0402]  218.46 120.32 0 top
RV24  -  [R_0402]  201.22 113.89 180 bottom
RV25  -  [R_0402]  172.11 140.2 90 top
RV26  -  [R_0402]  172.11 140.2 90 bottom
RV27  -  [R_0402]  200.31 115.67 0 bottom
RV28  -  [R_0402]  158.13 152.33 0 top
RV29  -  [R_0402]  169 141.11 270 bottom
RV30  -  [R_0402]  191.35 140.13 90 bottom
RV31  -  [R_0402]  191.35 140.13 90 top
RV32  -  [R_0402]  200.96 159.06 180 top
RV33  -  [R_0402]  200.04 157.28 0 top
RV34  -  [R_0402]  159.05 154.1 180 top
RV35  -  [R_0402]  177.07 159.31 270 bottom
RV36  -  [R_0402]  178.84 158.4 90 bottom
RV37  -  [R_0402]  169.89 140.2 90 bottom
RV38  -  [R_0402]  177.07 159.31 270 top
RV39  -  [R_0402]  187.35 141.05 270 bottom
RV40  -  [R_0402]  200.5 157.99 270 bottom
RV41  -  [R_0402]  202.34 157.07 90 bottom
RV42  -  [R_0402]  172.62 128.88 90 top
RV43  -  [R_0402]  173.51 128.88 90 top
RV44  -  [R_0402]  186.16 129.27 180 top
RV45  -  [R_0402]  186.16 130.16 180 top
RV46  -  [R_0402]  186.39 128.26 0 top
RV47  -  [R_0402]  190.85 128.84 270 top
RV48  -  [R_0402]  187.47 117.78 0 top
RV49  -  [R_0402]  190.16 117.78 180 top
RV54  -  [R0603_0OHM]  44.99 16.94 180 top
RV59  -  [R0603_0OHM]  31.91 29.96 270 top
RV64  -  [R_0402]  178.32 108 0 top
RV66  -  [R_0402]  161.72 114.55 180 bottom
RV67  -  [R_0402]  194.27 101.57 90 bottom
RV68  -  [R_0402]  194.27 104.26 270 bottom
RV69  -  [R_0402]  191.8 101.57 90 bottom
RV70  -  [R_0402]  191.8 104.26 270 bottom
RV71  -  [R_0402]  192.88 101.57 90 bottom
RV73  -  [R_0402]  190.86 104.25 180 bottom
RV74  -  [R_0402]  189.97 100.38 180 bottom
RV75  -  [R_0402]  181.7 98.65 90 bottom
RV76  -  [R_0402]  182.59 98.65 90 bottom
RV81  -  [R_0402]  183.48 98.65 90 bottom
RV82  -  [R_0402]  184.37 98.65 90 bottom
RV83  -  [R_0402]  185.26 98.65 90 bottom
RV84  -  [R_0402]  158.51 114.54 0 bottom
RV85  -  [R_0402]  187.29 107.93 90 top
RV89  -  [R_0402]  181.64 106.42 270 top
RV90  -  [R_0402]  179.92 95.41 90 top
RV91  -  [R_0402]  175.16 94.55 270 top
RV93  -  [R_0402]  185.01 102.47 180 bottom
RV95  -  [R_0402]  185.01 103.36 180 bottom
RV96  -  [R_0402]  175.36 98.36 270 bottom
RV97  -  [R_0402]  171.43 104.06 180 bottom
RV98  -  [R_0402]  175.36 95.69 90 bottom
RV103  -  [R_0805]  168.3 129.87 270 top
RV105  -  [R_0402]  175.54 160.5 90 bottom
RV107  -  [R_0402]  189.26 94.14 90 bottom
RV108  -  [R_0402]  189.26 95.92 90 bottom
RV109  -  [R_0402]  173.31 94.6 0 bottom
RV118  -  [R0402_0OHM]  160.56 106.43 270 top
RV119  -  [R0402_0OHM]  182.54 101.14 180 bottom
RV120  -  [R0402_0OHM]  157.45 107.99 90 top
RV121  -  [R0402_0OHM]  186.86 101.21 180 bottom
RV122  -  [R_0402]  183.22 104.26 270 bottom
RV123  -  [R_0402]  173.11 106.28 0 top
RV124  -  [R0402_0OHM]  156.56 105.51 90 top
RV125  -  [R_0402]  178.07 112.57 0 top
RV126  -  [R0402_0OHM]  157.57 102.34 90 top
RV127  -  [R_0402]  161.84 109.84 180 bottom
RV133  -  [R_0402]  169.69 117.84 0 top
RV136  -  [R_0402]  193.43 95.36 0 top
RV137  -  [R_0402]  192.44 93.52 180 top
RV138  -  [R_0402]  210.91 101.06 90 top
RV139  -  [R_0402]  162.03 132.64 180 bottom
RV140  -  [R_0402]  162.02 133.58 180 bottom
RV141  -  [R_0402]  196.14 103.5 90 bottom
RV142  -  [R_0402]  197.96 107.05 90 bottom
RV143  -  [R_0402]  209.96 101.98 270 top
RV144  -  [R_0402]  207.61 101.38 90 top
RV145  -  [R_0402]  206.66 101.38 90 top
RV146  -  [R_0402]  161.11 131.75 0 bottom
RV147  -  [R_0402]  161.11 134.47 0 bottom
RV148  -  [R_0402]  197.09 105.28 90 bottom
RV149  -  [R_0402]  197.07 107.96 270 bottom
RV162  -  [R_0402]  200.55 129.4 0 top
RV163  -  [R_0402]  200.5 131.69 0 bottom
RV169  -  [R_0402]  200.31 112.56 0 top
RV171  -  [R_0402]  200.31 112.56 0 bottom
RV181  -  [R_0402]  178.84 158.4 90 top
RV183  -  [R_0402]  169.89 140.2 90 top
RV184  -  [R_0402]  168.11 141.11 270 top
RV185  -  [R_0402]  158.13 151.44 0 top
RV186  -  [R_0402]  159.05 149.66 180 top
RV191  -  [R_0402]  181.51 158.28 90 top
RV192  -  [R_0402]  179.73 158.28 90 top
RV193  -  [R_0402]  189.13 140.13 90 top
RV194  -  [R_0402]  187.35 141.05 270 top
RV195  -  [R_0402]  182.4 159.07 270 bottom
RV196  -  [R_0402]  180.62 158.15 90 bottom
RV197  -  [R_0402]  189.13 140.13 90 bottom
RV198  -  [R_0402]  171.22 121.45 90 top
RV199  -  [R_0402]  182.54 96.37 180 top
RV201  -  [R_0402]  154.99 112.2 270 top
RV202  -  [R_0402]  173.4 117.73 180 top
RV203  -  [R_0402]  164.49 101 270 top
RV204  -  [R_0402]  172.82 114.35 180 top
RV206  -  [R_0402]  176.25 127.79 180 top
RV207  -  [R_0402]  166.22 114.09 180 top
RV215  -  [R_0402]  179.11 109.46 180 top
RV234  -  [R_0603]  165.26 128.51 180 top
RV235  -  [R_0402]  175.92 103.28 90 bottom
RV236  -  [R_0402]  174.91 104.2 270 bottom
RV237  -  [R_0402]  166.38 101 270 top
RV238  -  [R_0402]  168.24 100.08 90 top
RV239  -  [R_0402]  158.4 111.28 90 top
RV240  -  [R_0402]  159.28 112.2 270 top
RV241  -  [R_0402]  160.81 114.55 270 top
RV242  -  [R_0402]  158.52 113.63 90 top
RV243  -  [R_0402]  156.87 111.28 90 top
RV244  -  [R_0402]  154.33 117.15 270 top
RV245  -  [R_0402]  153.38 117.15 270 top
RV246  -  [R_0402]  171.36 112.76 180 top
RV247  -  [R_0402]  167.02 110.41 0 top
RV248  -  [R0402_0OHM]  167.02 109.46 0 top
RV250  -  [R_0402]  188.16 104.25 0 bottom
RV251  -  [R_0402]  177.13 103.28 90 bottom
RV252  -  [R_0402]  178.08 103.28 90 bottom
RX2  -  [R_0402]  227.14 178.54 90 top
RX3  -  [R_0402]  226.25 179.45 270 top
RX4  -  [R0805_0OHM]  202.05 166.21 180 bottom
RX5  -  [R_0402]  198.42 168.73 0 top
RX6  -  [R_0402]  199.25 165.13 90 bottom
RX7  -  [R0402_0OHM]  216.32 171.71 180 top
RX8  -  [R_0402]  216.32 172.66 180 top
RX9  -  [R_0402]  216.32 170.75 180 top
RX12  -  [R_0402]  15.09 112.56 180 bottom
RX13  -  [R_0402]  22.95 110.36 270 bottom
RX14  -  [R_0402]  19.19 117.27 0 bottom
RX15  -  [R_0402]  15.09 114.35 180 bottom
RX16  -  [R_0402]  14.02 110.28 90 top
RX17  -  [R_0402]  14.02 109.41 270 top
RX18  -  [R_0402]  219.5 178.11 0 top
RX19  -  [R0402_0OHM]  222.18 179.01 270 top
RX20  -  [R0402_0OHM]  220.41 178.98 180 top
RX21  -  [R_0402]  218.98 167.11 90 top
RX22  -  [R_0402]  219.87 167.11 90 top
RX23  -  [R_0402]  221.29 179.01 270 top
RX25  -  [R_0402]  197.63 173.13 180 top
RX26  -  [R_0402]  203.99 167.31 270 bottom
RX27  -  [R0603_0OHM]  225.71 175.82 0 top
RX30  -  [R_0402]  196.69 174.35 0 top
RX31  -  [R_0402]  198.38 165.13 90 bottom
RX33  -  [R_0402]  204.68 179.38 0 top
RX34  -  [R_0402]  14.19 115.23 90 bottom
RX35  -  [R_0402]  199.3 174.45 180 bottom
RX36  -  [R_0402]  206.65 167.31 270 bottom
RX37  -  [R_0402]  201.17 174.37 0 bottom
RX38  -  [R_0402]  206.98 174.08 0 bottom
RX39  -  [R_0402]  201.17 173.48 0 bottom
RX40  -  [R_0402]  206.98 173.19 0 bottom
RX41  -  [R_0402]  201.17 172.61 0 bottom
RX42  -  [R_0402]  206.98 172.3 0 bottom
RX43  -  [R_0402]  201.17 171.72 0 bottom
RX44  -  [R_0402]  206.98 171.41 0 bottom
RX45  -  [R_0402]  201.17 170.83 0 bottom
RX46  -  [R_0402]  206.98 170.53 0 bottom
RX47  -  [R_0402]  201.17 169.94 0 bottom
RX48  -  [R_0402]  206.98 169.64 0 bottom
RX49  -  [R_0402]  205.76 167.31 270 bottom
RX50  -  [R_0402]  213.58 164.01 0 bottom
RX51  -  [R_0402]  207.53 166.4 90 bottom
RX52  -  [R_0402]  199.3 173.56 180 bottom
RX53  -  [R_0402]  216.18 179.01 0 top
RX168  -  [R_0402]  198.97 179.09 270 bottom
RX169  -  [R_0402]  198.97 176.39 90 bottom
RX170  -  [R_0402]  199.86 178.17 90 bottom
RX171  -  [R_0402]  199.86 177.31 270 bottom
SW1  -  [SW_SMT1-05-A_4P]  196.77 29.44 90 top
SW2  -  [SW_SMT1-05-A_4P]  202.92 42 180 bottom
T38  -  [TPC12]  110.7 116.36 0 top
T39  -  [TPC12]  88.61 119.18 180 bottom
T40  -  [TPC12]  91.66 120.23 0 top
T41  -  [TPC12]  94.14 120.7 0 top
T42  -  [TPC12]  87.47 120.08 180 bottom
T43  -  [TPC12]  94.26 118.92 0 top
T44  -  [TPC12]  92.9 114.61 0 top
T45  -  [TPC12]  94.26 114.48 0 top
T46  -  [TPC12]  94.26 115.94 0 top
T47  -  [TPC12]  86.22 111.71 180 bottom
T48  -  [TPC12]  92.95 116.12 0 top
T49  -  [TPC12]  93.62 113.26 0 top
T50  -  [TPC12]  95.24 119.85 0 top
T51  -  [TPC12]  94.26 117.46 0 top
T53  -  [TPC12]  122.01 122.67 0 top
T55  -  [TPC12]  122.96 111.17 0 top
T56  -  [TPC12]  125.38 116 0 top
T58  -  [TPC12]  123.22 114.43 0 top
T59  -  [TPC12]  125.68 114.56 0 top
T78  -  [TPC12]  183.9 113.69 270 top
T79  -  [TPC12]  175.12 112.14 270 top
T80  -  [TPC12]  170.71 118.92 270 top
T81  -  [TPC12]  171 120.18 270 top
T82  -  [TPC12]  161.84 137.59 90 bottom
T83  -  [TPC12]  193.32 104.51 90 bottom
T84  -  [TPC12]  164.87 104.12 90 bottom
T85  -  [TPC12]  160.96 115.66 180 bottom
T86  -  [TPC12]  162.82 114.91 180 bottom
T87  -  [TPC12]  162.31 113.58 180 bottom
T88  -  [TPC12]  163.03 117.24 180 bottom
T89  -  [TPC12]  161.7 116.91 180 bottom
T90  -  [TPC12]  173.14 112.08 0 top
T91  -  [TPC12]  172.79 113.31 0 top
T94  -  [TPC12]  40.78 80.61 180 bottom
T95  -  [TPC12]  40.29 84.19 180 bottom
T96  -  [TPC12]  43.59 81.68 180 bottom
T97  -  [TPC12]  133.62 114.71 180 bottom
T98  -  [TPC12]  134.9 115.11 180 bottom
T99  -  [TPC12]  133.58 113.3 180 bottom
T102  -  [TPC12]  126.98 113.61 0 top
T103  -  [TPC12]  136.3 100.32 0 top
T104  -  [TPC12]  126.9 111.75 0 top
T105  -  [TPC12]  128.24 111.38 0 top
T106  -  [TPC12]  132.69 108.63 180 bottom
T107  -  [TPC12]  125.44 113.1 0 top
T111  -  [TPC12]  89.21 124.42 0 top
T112  -  [TPC12]  88.61 123.75 180 bottom
T113  -  [TPC12]  94.1 122.09 0 top
T114  -  [TPC12]  90.52 124.32 0 top
T115  -  [TPC12]  92.84 120.79 0 top
T116  -  [TPC12]  92.74 122.42 0 top
T117  -  [TPC12]  128.25 114.37 0 top
T118  -  [TPC12]  122.96 101.48 0 top
T119  -  [TPC12]  124.27 109.3 0 top
T120  -  [TPC12]  121.95 124.64 0 top
T121  -  [TPC12]  122.57 126.63 0 top
T124  -  [TPC12]  128.37 119.51 0 top
T125  -  [TPC12]  133.45 116.46 180 bottom
T126  -  [TPC12]  128.35 112.96 0 top
T127  -  [TPC12]  128.36 109.91 0 top
T128  -  [TPC12]  134.99 107.33 180 bottom
T129  -  [TPC12]  115.58 120.93 0 top
T130  -  [TPC12]  113.38 118.77 0 top
T131  -  [TPC12]  110.1 118.84 0 top
T132  -  [TPC12]  102.65 101.92 180 bottom
T133  -  [TPC12]  124.54 120.13 0 top
T134  -  [TPC12]  105.54 102.28 180 bottom
T135  -  [TPC12]  122.74 128.39 0 top
T136  -  [TPC12]  131.74 110.33 180 bottom
T137  -  [TPC12]  123.03 109.86 0 top
T138  -  [TPC12]  118.08 124.83 0 top
T139  -  [TPC12]  134.62 100.56 0 top
T140  -  [TPC12]  117.44 123.62 0 top
T141  -  [TPC12]  125.01 100.68 0 top
T142  -  [TPC12]  123.64 103.14 0 top
T143  -  [TPC12]  118.65 121.34 0 top
T144  -  [TPC12]  124.27 100.47 180 bottom
T145  -  [TPC12]  124.23 101.91 180 bottom
T146  -  [TPC12]  88.56 103.43 180 bottom
T147  -  [TPC12]  86.44 100.59 180 bottom
T148  -  [TPC12]  87.56 126.94 180 bottom
T149  -  [TPC12]  88.55 126.01 180 bottom
T150  -  [TPC12]  104.73 131.92 180 bottom
T151  -  [TPC12]  98.3 130.72 180 bottom
T152  -  [TPC12]  99.98 130.74 180 bottom
T153  -  [TPC12]  88.61 121.02 180 bottom
T154  -  [TPC12]  92.89 119.36 0 top
T155  -  [TPC12]  116.11 114.37 0 top
T156  -  [TPC12]  116.79 117.34 0 top
T157  -  [TPC12]  88.89 99 180 bottom
T158  -  [TPC12]  93.31 130.63 180 bottom
T159  -  [TPC12]  131.3 130.52 180 bottom
T160  -  [TPC12]  119.32 119.95 0 top
T161  -  [TPC12]  133.29 125.54 180 bottom
T162  -  [TPC12]  120.03 118.13 0 top
T163  -  [TPC12]  134.23 126.48 180 bottom
T164  -  [TPC12]  118.14 122.54 0 top
T165  -  [TPC12]  119.1 123.64 0 top
T166  -  [TPC12]  91.11 101.89 180 bottom
T167  -  [TPC12]  134.08 129.9 180 bottom
T168  -  [TPC12]  135.74 130.51 180 bottom
T169  -  [TPC12]  89.31 131.82 180 bottom
T170  -  [TPC12]  88.62 129.59 180 bottom
T171  -  [TPC12]  133.8 106.66 180 bottom
T172  -  [TPC12]  133.32 105.21 180 bottom
T173  -  [TPC12]  88.94 96.87 180 bottom
T174  -  [TPC12]  126.97 115.5 0 top
T175  -  [TPC12]  127.05 120.21 0 top
T176  -  [TPC12]  125.96 122.1 0 top
T177  -  [TPC12]  126.14 119.24 0 top
T178  -  [TPC12]  125.61 120.86 0 top
T179  -  [TPC12]  132.01 122.52 180 bottom
T180  -  [TPC12]  132.93 123.6 180 bottom
T181  -  [TPC12]  134.41 124.78 180 bottom
T182  -  [TPC12]  126.46 110.54 0 top
T183  -  [TPC12]  171.83 83.72 180 bottom
T184  -  [TPC12]  168.87 82 180 bottom
T185  -  [TPC12]  177.3 81.87 180 bottom
T186  -  [TPC12]  174.46 82.77 180 bottom
TL1  -  [BOTH_NS0013LF_16P]  30.91 90.67 270 bottom
U2301  -  [TPS22966DPUR_SON14_2X3]  192.49 21.08 270 top
U2302  -  [W25Q64FVSSIG_SO8]  168.05 84.08 180 bottom
U2303  -  [74AUP1G07GW_TSSOP5]  79.92 54.14 270 top
U2304  -  [TPS22966DPUR_SON14_2X3]  140.75 25.63 0 top
UA1  -  [ALC3221-CG_MQFN48_6X6]  42.31 22.62 90 top
UC1  -  [HASWELL-MCP-E-ULT_BGA_1168P-T]  130.28 127.57 0 bottom
UC3  -  [MC74VHC1G08DFT2G_SC70-5]  148.44 107.94 180 top
UC4  -  [74CBTLV3126BQ_DHVQFN14_2P5X3]  71.1 108.54 270 bottom
UD1  -  [MC74VHC1G08DFT2G_SC70-5]  57.14 19.96 90 top
UE1  -  [KB9012QF-A2_LQFP128_14X14]  183.19 37.69 0 top
UE2  -  [SN74LVC1G06DCKR_SC70-5]  178.13 54.43 0 top
UE3  -  [G993P1UF_SOP8]  46.26 105.38 0 bottom
UG1  -  [SLG3NB274VTR_TQFN16_2X3]  62.32 44.43 0 top
UI2  -  [AP2301MPG-13_MSOP8]  27.49 50.43 0 top
UI3  -  [AP2301MPG-13_MSOP8]  27.42 66.11 0 top
UI4  -  [AP2301MPG-13_MSOP8]  20.34 32.99 90 top
UI5  -  [AP2301MPG-13_MSOP8]  215.05 40.79 270 bottom
UL1  -  [RTL8106E-CG_QFN32_4X4]  35.67 86.54 90 bottom
UL2  -  [APL3512ABI-TRG_SOT23-5]  49.51 86.92 270 bottom
UR1  -  [RTS5179-GR_QFN24_4X4]  175.82 22.77 0 top
UV1  -  [2160809000A11SEYMOU_FCBGA_962P]  192.86 135.1 180 bottom
UV3  -  [K4G20325FC-HC05_FBGA_170P]  195.6 154.8 270 top
UV4  -  [K4G20325FC-HC05_FBGA_170P]  162.28 154.86 270 bottom
UV5  -  [K4G20325FC-HC05_FBGA_170P]  175.09 154.86 270 top
UV6  -  [K4G20325FC-HC05_FBGA_170P]  182.79 154.8 270 bottom
UV7  -  [K4G20325FC-HC05_FBGA_170P]  215.16 128.72 180 top
UV8  -  [K4G20325FC-HC05_FBGA_170P]  215.16 141.52 180 bottom
UV9  -  [K4G20325FC-HC05_FBGA_170P]  214.97 108.32 180 top
UV10  -  [K4G20325FC-HC05_FBGA_170P]  214.97 121.12 180 bottom
UV13  -  [MC74VHC1G08DFT2G_SC70-5]  158.91 111.1 90 bottom
UV14  -  [ADM1032ARMZ-2REEL_MSOP8]  178.55 96.26 180 bottom
UX1  -  [APL3512ABI-TRG_SOT23-5]  218.45 172.78 270 top
UX2  -  [MC74VHC1G08DFT2G_SC70-5]  210.43 163.25 90 bottom
UX4  -  [RTD2136R-CG_QFN48_6X6]  201.27 174.59 270 top
YC1  -  [Y_Q13FC1350000_2P]  146.86 102.73 0 bottom
YC2  -  [Y_X3G024000DC1H_4P]  115.52 137.77 0 top
YG1  -  [Y_FSX3M-25PM20FDO_4P]  60.73 41.19 180 top
YL2  -  [Y_FSX3M-25PM20FDO_4P]  36.77 81.81 0 bottom
YV1  -  [Y_7V27000011_4P]  172.39 100.22 180 bottom

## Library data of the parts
C35-C38 C50-C58 C61-C64 C67-C69 C71 C73 C75-C77 C79-C81 C83 C85 C87 C88 C2326 C2327 C5212 CA21 CA22 CA24 CA25 CA29-CA33 CA38-CA40 CA51 CA54 CA56 CA58 CA60 CA65 CA69 CC14 CC15 CC23 CC25 CC27-CC35 CC40 CD31 CD63 CD64 CE5 CE6 CE11 CE12 CE15 CE18-CE20 CE23 CE24 CE26-CE36 CG1-CG4 CG7-CG11 CI2-CI4 CI7 CI9-CI11 CI13-CI17 CI19 CI22 CI24-CI26 CI30 CI32 CL15 CL19 CL20 CL22 CL26 CL30 CL31 CL34-CL37 CL39 CL41 CM40 CM44 CM46-CM49 CR1 CR3-CR7 CR9-CR11 CS5 CS6 CS8-CS11 CS13-CS15 CS17 CS105 CS106 CS108 CS109 CV8-CV40 CV43-CV50 CV59-CV76 CV78 CV79 CV81 CV83-CV85 CV87-CV89 CV92-CV95 CV108 CV109 CV112-CV115 CV118 CV119 CV121 CV122 CV124-CV130 CV132 CV133 CV141-CV150 CV152-CV156 CV171-CV174 CV188-CV190 CV193-CV196 CV198 CV199 CV201-CV212 CV216-CV224 CV280 CV281 CV283-CV288 CV290-CV299 CV301-CV308 CV310-CV313 CV315 CV316 CV318 CV319 CV325 CV326 CV328-CV333 CV335 CV349-CV356 CV368-CV401 CX1 CX2 CX4 CX9-CX21 CX23-CX34 CX37-CX44 CX46 CX47 PC1-PC5 PC7 PC8 PC13-PC16 PC102 PC104 PC108 PC110 PC113 PC114 PC201-PC203 PC207 PC208 PC210 PC300 PC303 PC304 PC307 PC401 PC403 PC404 PC501 PC502 PC504 PC506 PC507 PC509-PC514 PC519-PC523 PC601 PC603 PC604 PC702 PC705 PC708 PC711 PC715 PC717 PC719 PC720 PC722 PC723 PC806 PC809 PC813 PC814 PC816-PC821 PC831 PC832 PC840-PC866 PC869 PC871-PC873 PC1100 PC1101 PC1104 PC1106 PC1200 PC1203 PC1209 PC1214 PC1302 PC1304 PC1306 PC1307 = C_0402
C39-C45 C60 C66 C72 C74 C78 C82 C2305 C2306 C2308 C2309 C2311-C2314 C2316 C2318 C2322-C2324 CA1 CA2 CA23 CA53 CA55 CA57 CA59 CA61-CA64 CA67 CA68 CA71 CA74 CC26 CD59 CD62 CE22 CE25 CE56-CE58 CG6 CI40 CI43 CI44 CL38 CM43 CM45 CR2 CR8 CS16 CV1 CV3-CV7 CV41 CV42 CV77 CV80 CV82 CV86 CV91 CV101-CV103 CV110 CV111 CV116 CV117 CV120 CV123 CV131 CV134 CV136-CV140 CV151 CV170 CV187 CV197 CV200 CV213-CV215 CV322-CV324 CX5 CX22 CX35 CX45 PC100 PC103 PC105 PC106 PC109 PC111 PC200 PC204 PC209 PC301 PC302 PC312 PC313 PC503 PC505 PC508 PC701 PC706 PC707 PC709 PC710 PC721 PC803 PC807 PC810 PC811 PC815 PC835 PC867 PC868 PC870 PC1103 PC1105 PC1205 PC1210 PC1212 PC1213 = C_0603
C59 C65 C70 C84 C86 CL33 = C_1206
C2307 C2310 CE16 CG5 CI6 CI12 CI18 CI21 CI23 CI27 CI31 CS7 CS12 CV97 CX3 CX7 CX8 CX36 CX48 PC112 PC115 PC205 PC206 PC211 PC212 PC305 PC306 PC308-PC311 PC400 PC402 PC405 PC517 PC518 PC600 PC602 PC605 PC703 PC704 PC712-PC714 PC716 PC718 PC804 PC805 PC808 PC901-PC923 PC1102 PC1201 PC1202 PC1204 PC1206 PC1207 PC1211 PC1300 PC1301 PC1303 PC1305 PC1308 = C_0805
CC1-CC11 CC13 CC16-CC22 CC24 = C_0402: room: CPU
CD1-CD11 CD21-CD27 CD30 CD32-CD42 CD52-CD57 CD60 CD61 = C_0402: room: MEMORY
CD12-CD14 CD16-CD20 CD28 CD29 CD43-CD50 CD58 = C_0603: room: MEMORY
CD15 CD51 = C_D3: room: MEMORY
CE1 CE2 = C_0402: room: EDP
CE7-CE9 = C_0402: room: DOCK
CI1 CI8 CI20 PC101 PC107 = C_MP6VLPS220MC4R2
CMOS1 ME1 = SHORTPADS: User Part Number: PART#; room: CPU
CV135 = C_B2
CV327 = C_D2
DA8 = BAT54C-7-F_SOT23-3
DA10 DA12 = AZ5125-02SPR7G_SOT23-3
DC1 = BAT54CW_SOT323-3
DE1 PD101 = L03ESDL5V0CG3-2_SOT-523-3
DH1 DX1 PD701 = RB751V-40_SOD323-2
DI1 DI4 = IP4292CZ10-TBR_XSON10_2P5X1
DI2 DI5 DI7 = L30ESDL5V0C3-2_SOT23-3
FD1-FD4 = FIDUCIAL_C40M80: room: LED
FE1 = F_1812L075-24DR
FX1 = F_1206L150PR
H1 H2 H5 H8 H9 H12 H16 H17 = H_2P8: room: LED
H4 = H_5P0N: room: LED
H6 H10 = H_3P3: room: LED
H7 = H_3P3
H11 = H_2P8
